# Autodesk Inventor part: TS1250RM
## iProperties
Category: PARTsolutions
Created: 2011-08
Part Number: TS1250RM
Catalog Web Link: www.cadenas.de
Description: Trennsteg 1250 RV - Trennsteg RV
Document SubType Name: Modeling
Designer: PARTsolutions
Density: 1 g/cm^3
Mass: 14.5742 g
Surface Area: 90.1903 cm^2
Volume: 14.5742 cm^3
NB: TS1250RM
NN: Trennsteg 1250 RV
NT: Trennsteg RV
NBSYN: TS1250RM
LINA: TS1250RM
TYP: TS1250RM
KT: DUMMY
SUPPLIER: Kabelschlepp
ARTICLENO: TS1250RM
BOMINFO: TS1250RM
CREATOR: CADENAS GmbH
PSOL_IDENT_0: {\\10.0.0.251\ps_data\23d-libs\kabelschlepp\4_eketten_st\trennstege\1250_ts_rm.prj},169 {VTYP=3D},{N
PSOL_IDENT_1: B=TS1250RM},{LINA=TS1250RM},{NN=Trennsteg 1250 RV},{DATE=31.05.2007 07:52:23},{GEOMDATE=07.02.2007 1
PSOL_IDENT_2: 2:31:00},{VERSION=},{LINEID=10},{LINESUBID=-1},{WBVAR=}  {NB=TS1250RM},{LINA=TS1250RM},{KT=DUMMY},{T
PSOL_IDENT_3: YP=TS1250RM}
Title: TS1250RM
Author: Cadenas PARTsolutions
Comments: Trennsteg RV
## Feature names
1. Extrusion1
2. Extrusion2
3. Extrusion3
4. Extrusion4
5. Extrusion5
6. Extrusion6
7. Extrusion7
